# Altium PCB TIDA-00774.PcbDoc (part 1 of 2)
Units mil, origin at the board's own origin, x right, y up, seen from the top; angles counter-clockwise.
Board outline 2559.06 x 2362.2 mil, 4 copper layers (Top Layer, GND, PWR, Bottom Layer), stack 79.834 mil thick; 133 components, 91 nets, 569 pads, 616 vias.
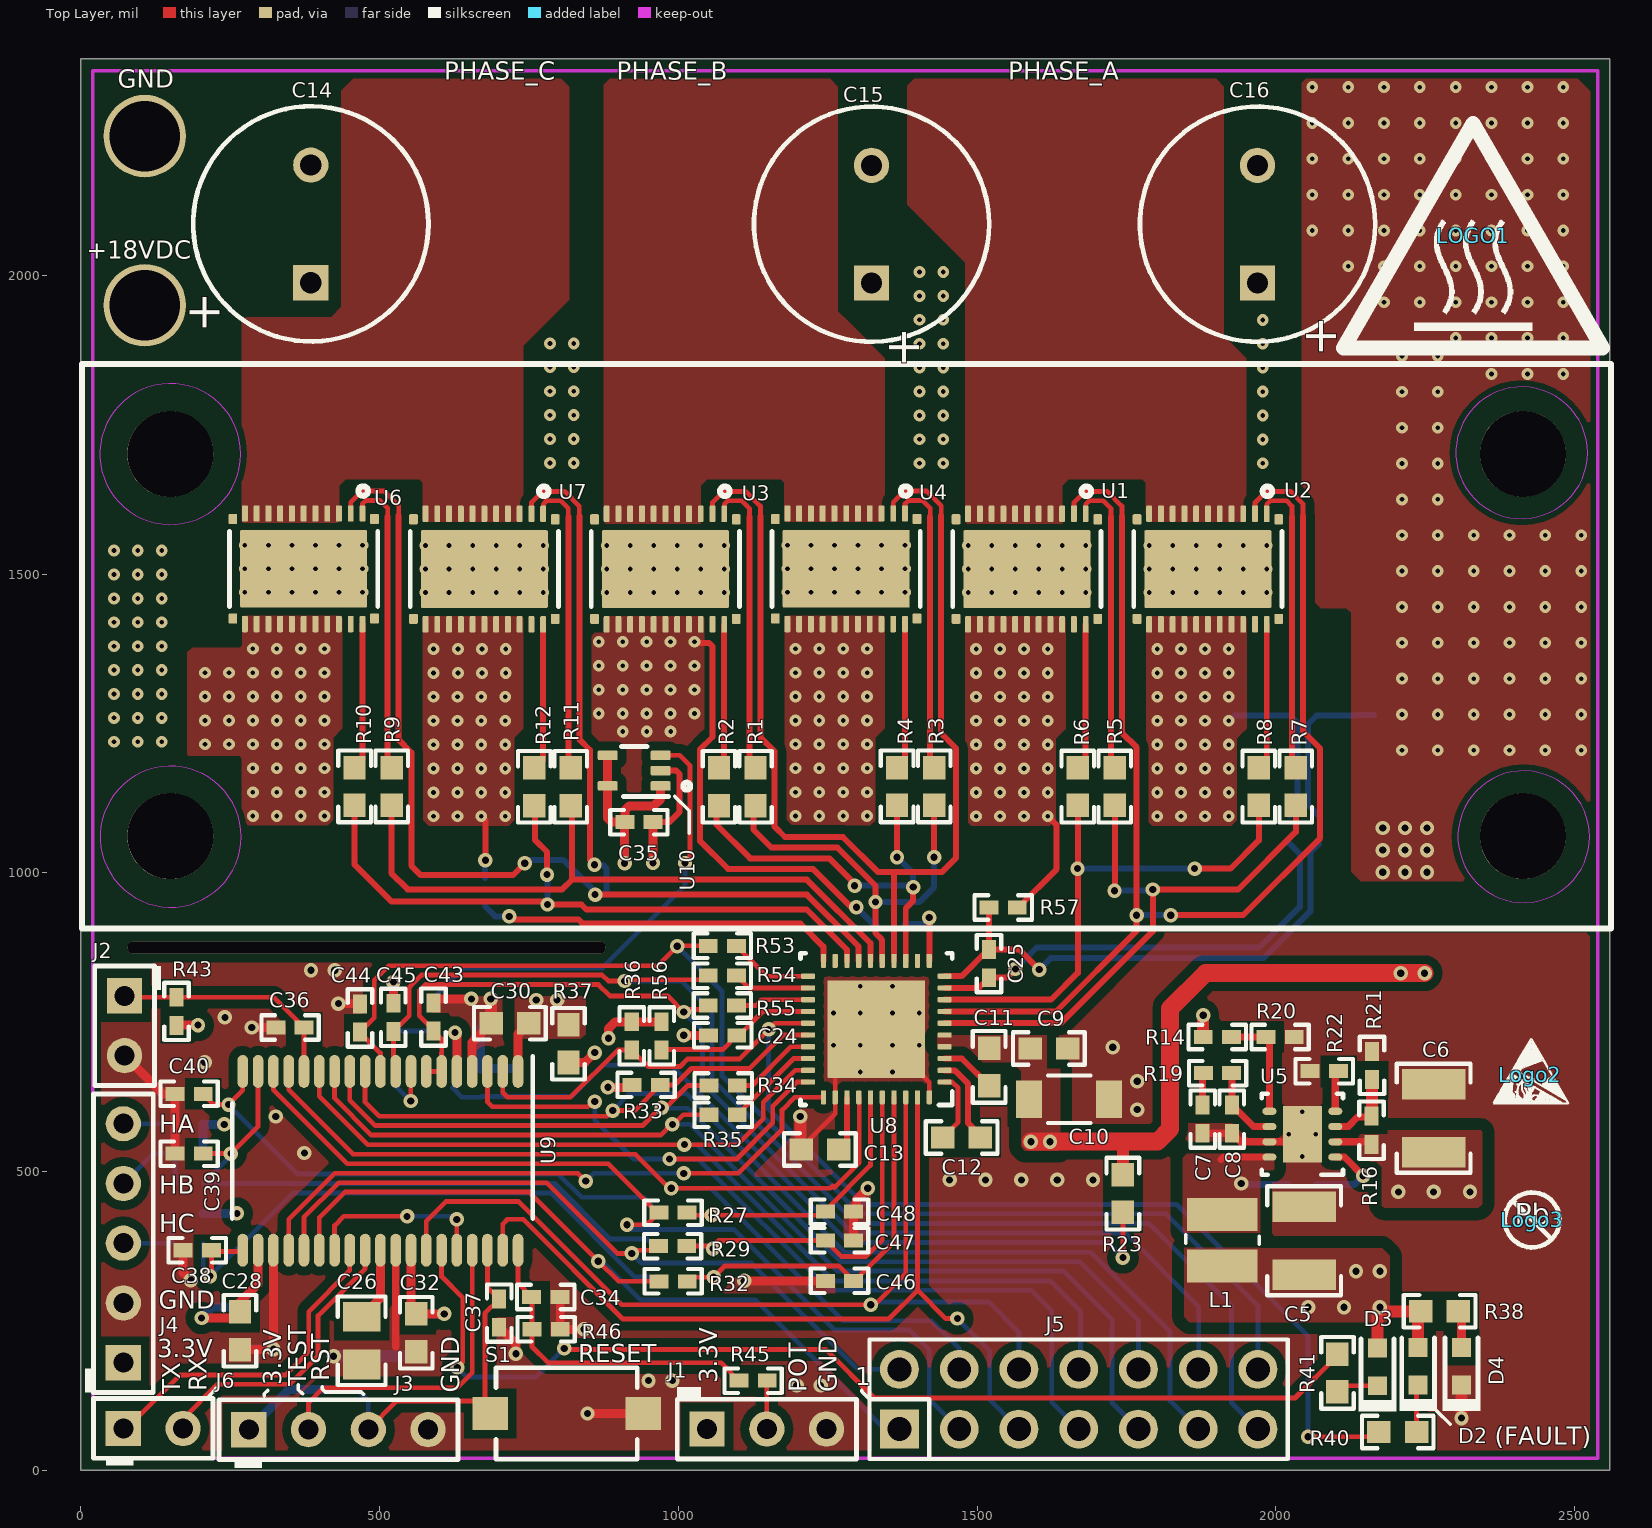
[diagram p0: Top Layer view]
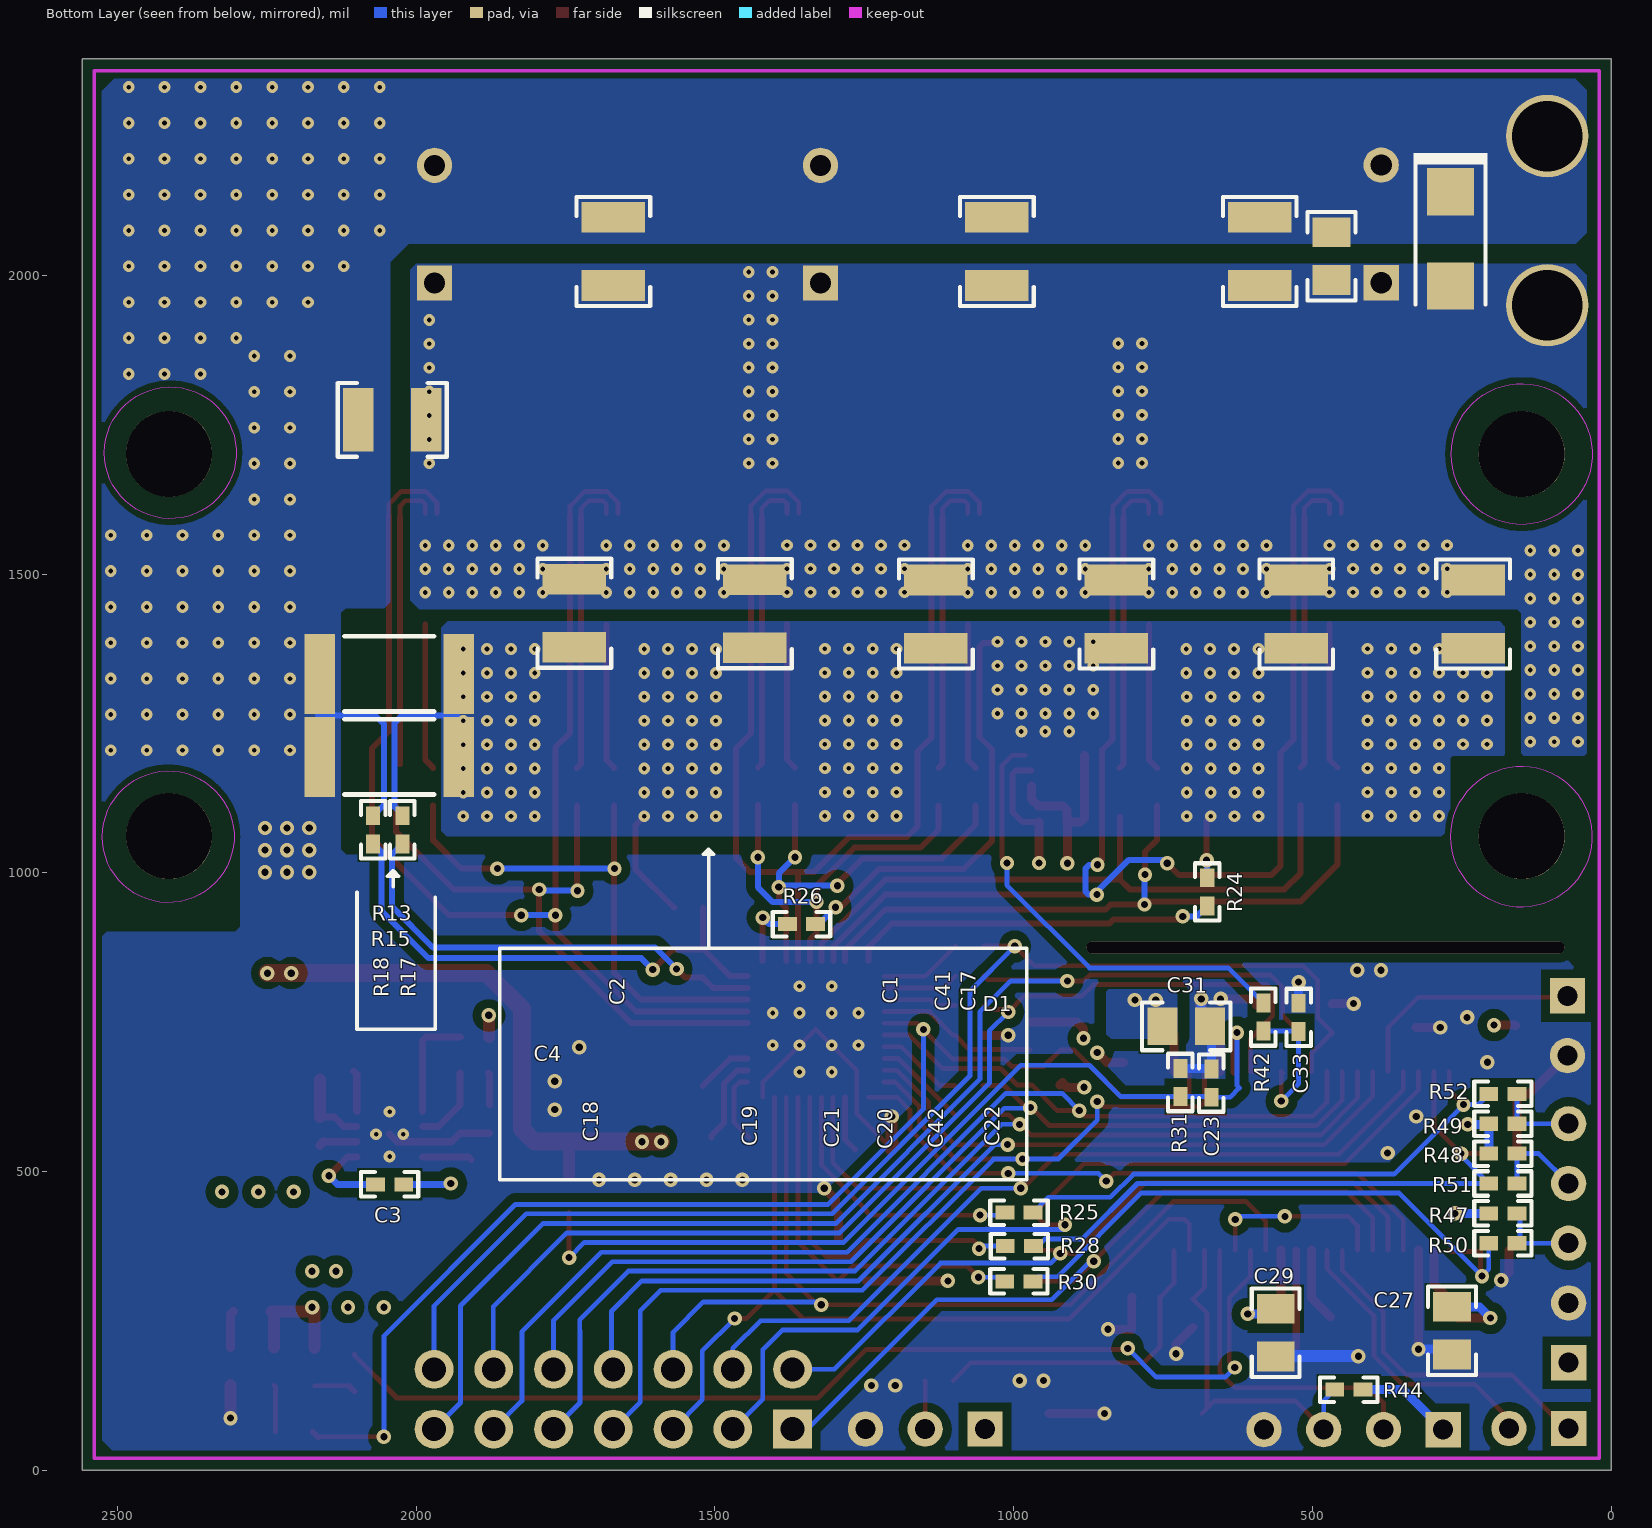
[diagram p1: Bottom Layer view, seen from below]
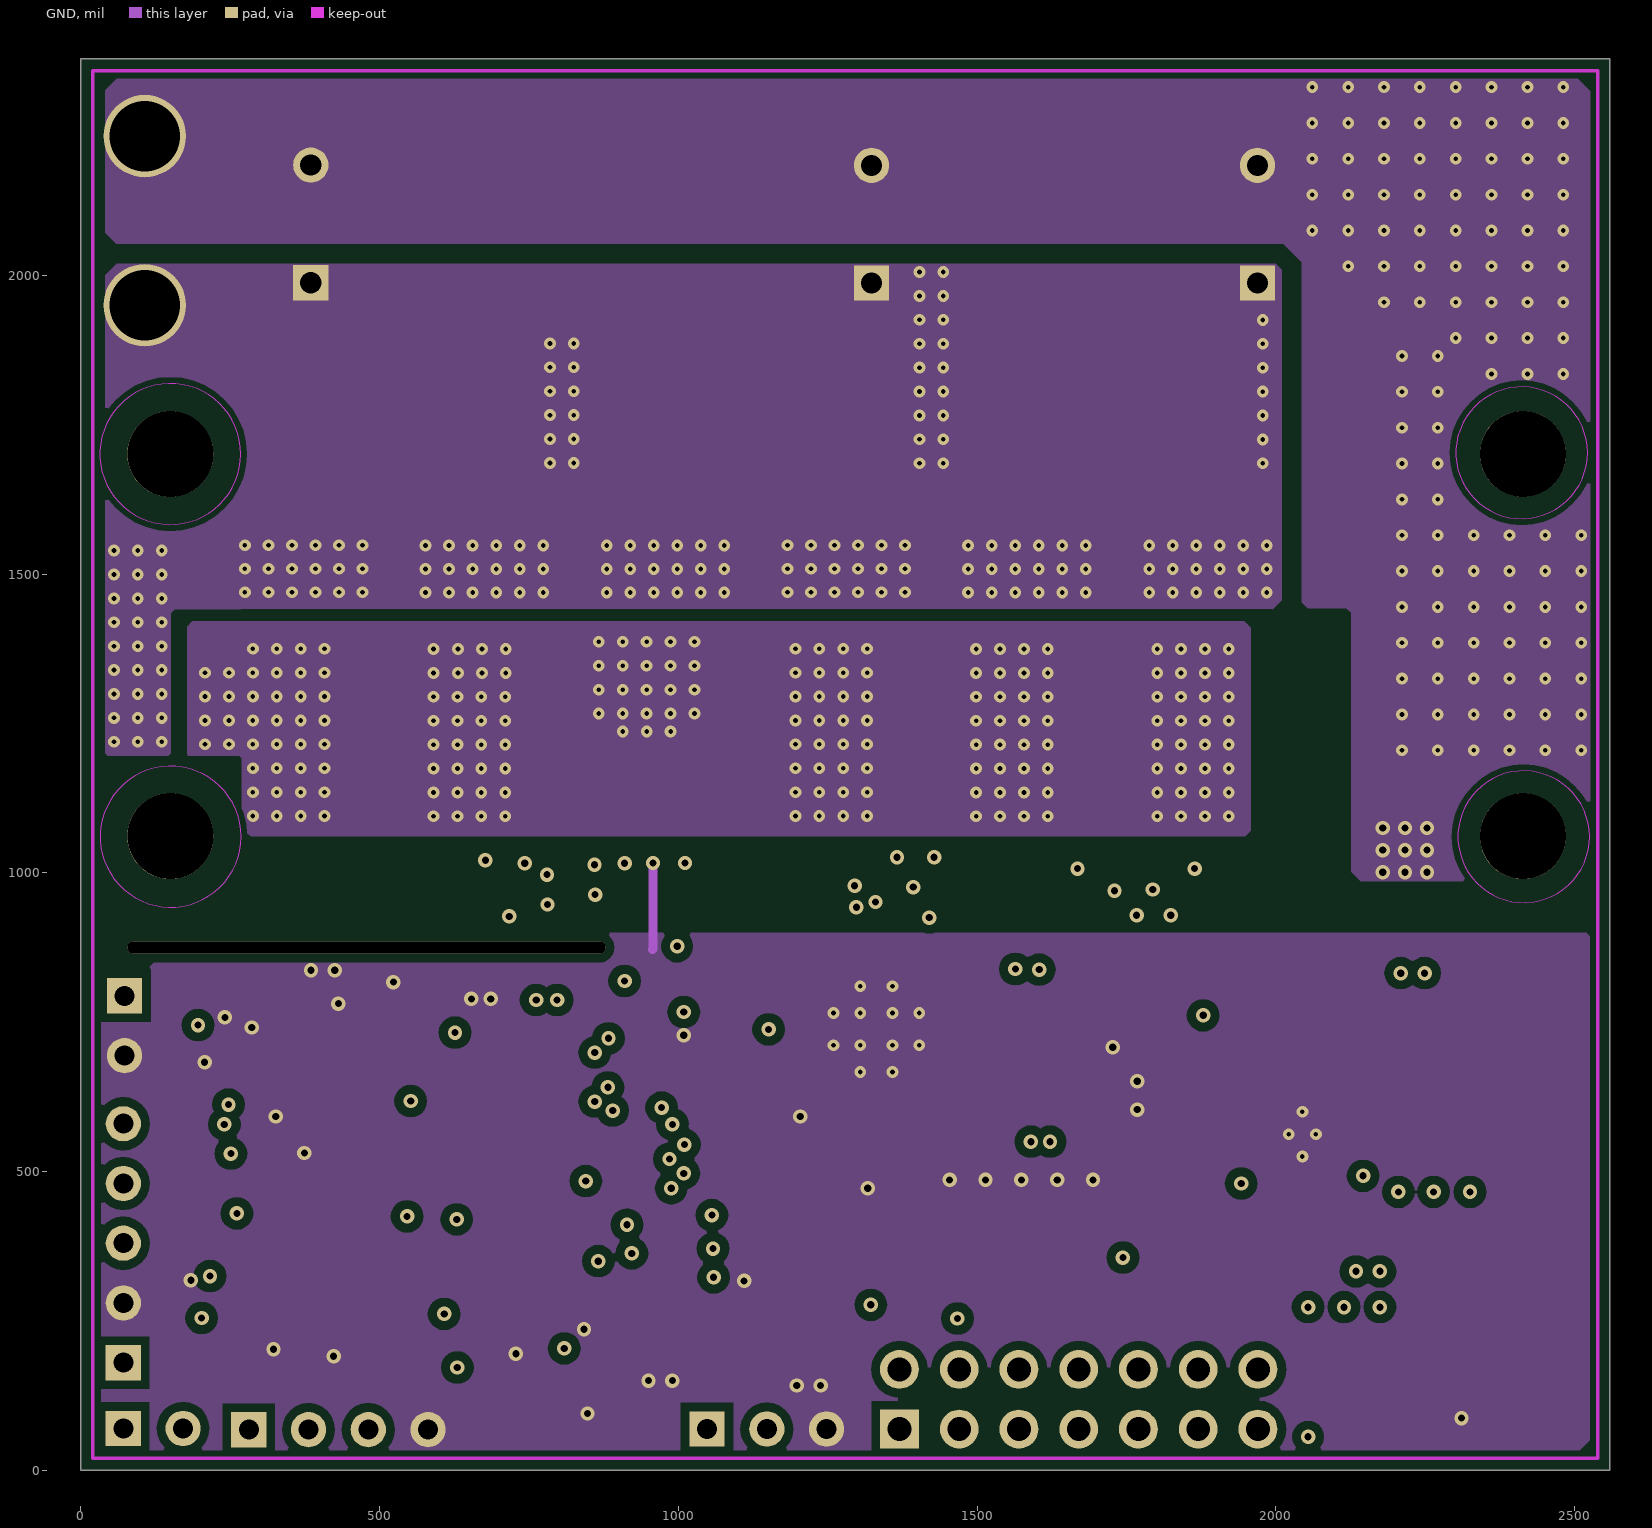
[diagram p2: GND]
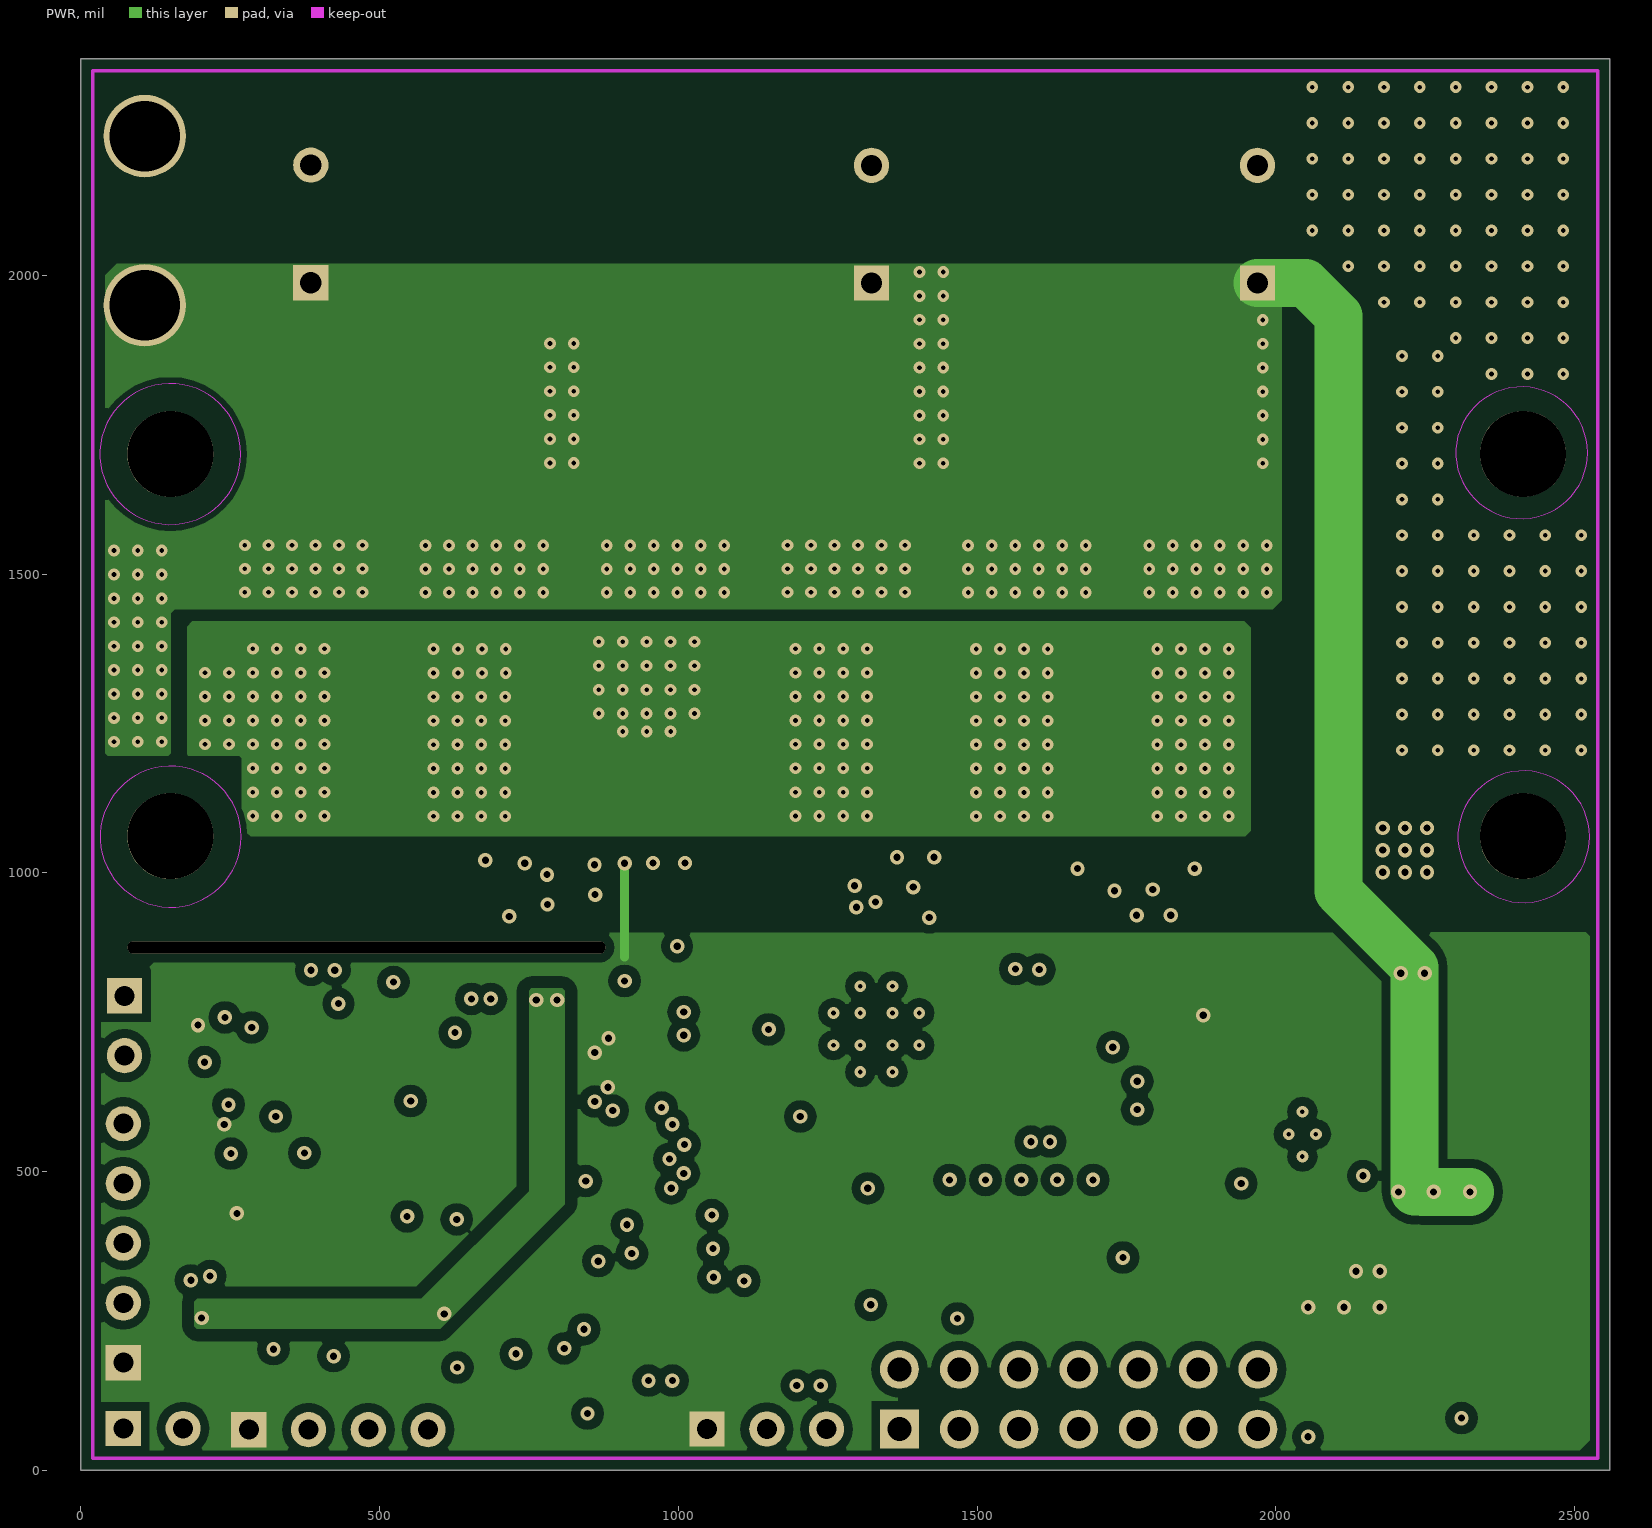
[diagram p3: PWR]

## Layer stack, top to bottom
Top Solder: solder mask 0.4, Solder Resist, Dk 3.5
Top Layer: signal copper 1.4
Dielectric1: core 59.2, FR-4, Dk 4.8
GND: signal copper 1.417
Dielectric 3: prepreg 5, Dk 4.2
PWR: signal copper 1.417
Dielectric 2: core 10, Dk 4.2
Bottom Layer: signal copper 1.4
Bottom Solder: solder mask 0.4, Solder Resist, Dk 3.5

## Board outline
0,0 2559.06,0 2559.06,2362.2 0,2362.2

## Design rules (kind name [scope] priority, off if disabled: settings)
AcuteAngle [All] p1: minimum=4.50000000000000E+0001 checktracksonly=FALSE
AssemblyTestPointUsage [All] p1: valid=2
Clearance Clearance_u1 [InPadClass('U1')] p1: gap=7.7
Clearance Clearance_Boardedge_poly [OnCopper and InPolygon vs IsKeepOut] p2: gap=10
Clearance Clearance_MTG_COPPER [InPadClass('MTG') vs InPolygon] p3: gap=40
Clearance "Shape to Shape" [InPolygon vs InPolygon] p4: gap=20
Clearance "shape to all" [InPolygon] p5: gap=15
Clearance "Clearance_via_thr pin" [IsVia vs IsThruPin] p6: gap=8
Clearance [All] p7: gap=7.8
DiffPairsRouting DiffPair_DiffPairsRouting [InDifferentialPair ('kan')] p1: maxlimit=10 minlimit=10 mostfreqgap=10 toplayer_minwidth=15 toplayer_maxwidth=15 toplayer_prefwidth=15 midlayer1_minwidth=15 midlayer1_maxwidth=15 midlayer1_prefwidth=15 midlayer2_minwidth=15 midlayer2_maxwidth=15 midlayer2_prefwidth=15 bottomlayer_minwidth=15 bottomlayer_maxwidth=15 bottomlayer_prefwidth=15 maxuncoupledlength=500
DiffPairsRouting DiffPair_DiffPairsRouting_1 [InDifferentialPair ('kan')] p2: maxlimit=10 minlimit=10 mostfreqgap=10 toplayer_minwidth=15 toplayer_maxwidth=15 toplayer_prefwidth=15 midlayer1_minwidth=15 midlayer1_maxwidth=15 midlayer1_prefwidth=15 midlayer2_minwidth=15 midlayer2_maxwidth=15 midlayer2_prefwidth=15 bottomlayer_minwidth=15 bottomlayer_maxwidth=15 bottomlayer_prefwidth=15 maxuncoupledlength=500
DiffPairsRouting [All] p3: maxlimit=100 minlimit=10 mostfreqgap=10 toplayer_minwidth=15 toplayer_maxwidth=15 toplayer_prefwidth=15 midlayer1_minwidth=15 midlayer1_maxwidth=15 midlayer1_prefwidth=15 midlayer2_minwidth=15 midlayer2_maxwidth=15 midlayer2_prefwidth=15 bottomlayer_minwidth=15 bottomlayer_maxwidth=15 bottomlayer_prefwidth=15 maxuncoupledlength=1000
FabricationTestPointUsage TestPointUsage [All] p1: valid=2 allowmultiple=FALSE
FabricationTestpoint Testpoint [All] p1: side=3 testpointundercomponent=TRUE minsize=40 maxsize=100 preferedsize=60 minholesize=0 maxholesize=40 preferedholesize=32 testpointgrid=1 allowsidetop=TRUE allowsidebottom=TRUE usegrid=TRUE gridtolerance=0.01
FanoutControl Fanout_LCC [IsLCC] p1: bgadir=Out bgaviamode=Centered fanoutstyle=Auto fanoutdirection=Alternating viagrid=1 // Fanout_LCC (Default Rule)
FanoutControl Fanout_BGA [IsBGA] p2: bgadir=Out bgaviamode=Centered fanoutstyle=Auto fanoutdirection=Alternating viagrid=1 // Fanout_BGA (Default Rule)
FanoutControl Fanout_Default [All] p4: bgadir=Out bgaviamode=Centered fanoutstyle=Auto fanoutdirection=Alternating viagrid=1 // Fanout_Default (Default Rule)
FanoutControl Fanout_Small [(CompPinCount < 5)] p5: bgadir=Out bgaviamode=Centered fanoutstyle=Auto fanoutdirection=OutThenIn viagrid=1 // Fanout_Small (Default Rule)
HoleSize [All] p1: absolutevalues=TRUE maxlimit=1000 minlimit=7 maxpercent=80.000 minpercent=20.000
MatchedLengths DiffPair_MatchedLengths [InDifferentialPair ('kan')] p1: tolerance=1000 checknetsindiffpair=TRUE checkdiffpairvsdiffpair=FALSE checkxsignals=FALSE checkothers=FALSE
MatchedLengths DiffPair_MatchedLengths_1 [InDifferentialPair ('kan')] p2: tolerance=1000 checknetsindiffpair=TRUE checkdiffpairvsdiffpair=FALSE checkxsignals=FALSE checkothers=FALSE
MinimumAnnularRing [All] p1: minimumring=5
MinimumAnnularRing MinimumAnnularRing_ThermalPadVias [IsVia and InAnyComponent] p2: minimumring=5.91
MinimumSolderMaskSliver MinimumSolderMaskSliver_Logo [InComponentClass('Logo') vs InComponentClass('Logo')] p1: minsoldermaskwidth=0.7
MinimumSolderMaskSliver [All] p2: minsoldermaskwidth=3.94
PlaneClearance [All] p1: clearance=15
PolygonConnect [All] p1: connectstyle=Direct reliefconductorwidth=10 reliefentries=4 polygonreliefangle="90 Angle" airgapwidth=10
RoutingVias RoutingVias_power [InNetClass('POWER')] p1: holewidth=16 width=32 viastyle="Through Hole" minholewidth=7.87 minwidth=19.68 maxholewidth=16 maxwidth=32
RoutingVias ThermalPadVias [IsVia and InAnyComponent] p2: holewidth=8 width=20 viastyle="Through Hole" minholewidth=7.87 minwidth=19 maxholewidth=12 maxwidth=24
RoutingVias [All] p3: holewidth=12 width=24 viastyle="Through Hole" minholewidth=7.87 minwidth=19.68 maxholewidth=16 maxwidth=32
SMDToCorner [All] p1: distance=30000
SilkToSilkClearance [All] p1: silktosilkclearance=5
SilkToSolderMaskClearance SilkscreenOverComponentPads [IsPad] p1: minsilkscreentomaskgap=0 clearancetoexposedcopper=TRUE
SolderMaskExpansion [All] p1: expansion=3
Width Width_power [InNetClass('pwr')] p1: maxlimit=200 minlimit=10 preferedwidth=20
Width [All] p2: maxlimit=100 minlimit=6 preferedwidth=10 checkconnectedcopper=TRUE
17 further rules are at their usual default settings.

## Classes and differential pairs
component class TIDA-00774_Page2: C3 C5 C6 C7 C8 C26 C27 C28 C29 C30 C31 C32 C33 C34 C35 C36 C37 C38 C39 C40 C? D2 D3 D4 J1 J2 J3 J4 J5 J6 L1 R14 R16 R19 R20 R21 R22 R37 R38 R40 R41 R42 R43 R44 R45 R46 R47 R48 R49 R50 R51 R52 R? S1 U5 U9 U10
component class TIDA-00774_Page1: C9 C10 C11 C12 C13 C14 C15 C16 C17 C23 C24 C25 C41 C43 C44 C45 C46 C47 C48 D1 R23 R24 R25 R26 R27 R28 R29 R30 R31 R32 R33 R34 R35 R36 R53 R54 R55 R56 R57 U8
component class AssemblyNote: ZZ1 ZZ2 ZZ3 ZZ4
component class TIDA-00774_Hardware: LOGO1 Logo2 Logo3 ZZ1 ZZ2 ZZ3 ZZ4
pad class U1: U1- U1-1 U1-2 U1-3 U1-4 U1-5 U1-6 U1-7 U1-8 U1-9 U1-10 U1-11 U1-12 U1-13 U1-14 U1-15 U1-16 U1-17 U1-18 U1-19 U1-20 U1-21 U1-22 U1-23 U1-24 U1-25 U1-26 U1-27 U2- U2-1 U2-2 U2-3 U2-4 U2-5 U2-6 U2-7 U2-8 U2-9 U2-10 U2-11 U2-12 U2-13 U2-14 U2-15 U2-16 U2-17 U2-18 U2-19 U2-20 U2-21 U2-22 U2-23 U2-24 U2-25 U2-26 U2-27 U3- U3-1 U3-2 U3-3 U3-4 U3-5 U3-6 U3-7 U3-8 U3-9 U3-10 U3-11 U3-12 U3-13 U3-14 U3-15 U3-16 U3-17 U3-18 U3-19 U3-20 U3-21 U3-22 U3-23 U3-24 U3-25 U3-26 U3-27 U4- U4-1 U4-2 U4-3 U4-4 U4-5 U4-6 U4-7 U4-8 U4-9 U4-10 U4-11 U4-12 U4-13 U4-14 U4-15 U4-16 U4-17 U4-18 U4-19 U4-20 U4-21 U4-22 U4-23 U4-24 U4-25 U4-26 U4-27 U6- U6-1 U6-2 U6-3 U6-4 U6-5 U6-6 U6-7 U6-8 U6-9 U6-10 U6-11 U6-12 U6-13 U6-14 U6-15 U6-16 U6-17 U6-18 U6-19 U6-20 U6-21 U6-22 U6-23 U6-24 U6-25 U6-26 U6-27 U7- U7-1 U7-2 U7-3 U7-4 U7-5 U7-6 U7-7 U7-8 U7-9 U7-10 U7-11 U7-12 U7-13 U7-14 U7-15 U7-16 U7-17 U7-18 U7-19 U7-20 U7-21 U7-22 U7-23 U7-24 U7-25 U7-26 U7-27 U9-39 U9-40 U9-41
component class TIDA-00774_Page3: C1 C2 C4 C18 C19 C20 C21 C22 C42 R1 R2 R3 R4 R5 R6 R7 R8 R9 R10 R11 R12 R13 R15 R17 R18 R? U1 U2 U3 U4 U6 U7 U?
component class Header: J1 J2 J4 J5 J6

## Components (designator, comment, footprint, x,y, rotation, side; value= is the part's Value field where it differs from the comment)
C1 "GRM32ER72A225KA35L" 1210#1 1028,2040 r90 bottom
C2 "GRM32ER72A225KA35L" 1210#1 1670,2040 r90 bottom
C3 "GRM155R71E103KA01D" 0402#1 2044.35,478.55 r0 bottom
C4 "GRM32ER72A225KA35L" 1210#1 2040,1758 r0 bottom
C5 "TMK325B7226KMHT" 1210_270 2047.36,384.24 r90 top
C6 "GRM32ER72A225KA35L" 1210#1 2264,589.31 r90 top
C7 "GRM155R71H821KA01D" 0402#1 1877.36,587.77 r270 top
C8 "CC0402JRNPO9BN150" 0402#1 1926.36,587.77 r270 top
C9 "06035C104KAT2A" 0603 1620,706 r0 top
C10 "GRM31CR71H475KA12L" 1206_180 1654,621 r180 top
C11 "C1608X7R1C105K" 0603 1520,675 r270 top
C12 "C0603C223K3RACTU" 0603 1474,557 r0 top
C13 "C1608X7R1C105K" 0603 1237,537 r180 top
C14 "35ZLG470MEFC10X20" CAPPR5-10X20 384.77,2086.09 r90 top
C15 "35ZLG470MEFC10X20" CAPPR5-10X20 1323.23,2085.61 r90 top
C16 "35ZLG470MEFC10X20" CAPPR5-10X20 1969.23,2085.61 r90 top
C17 "C2012X7R1E104K" 0805_HV 468,2032 r90 bottom
C18 "GRM32ER72A225KA35L" 1210#2 1735,1415 r270 bottom
C19 "GRM32ER72A225KA35L" 1210#2 1433,1414 r270 bottom
C20 "GRM32ER72A225KA35L" 1210#1 828,1433 r270 bottom
C21 "GRM32ER72A225KA35L" 1210#1 1130,1433 r270 bottom
C22 "GRM32ER72A225KA35L" 1210_270 231,1433 r270 bottom
C23 "885012105016" 0402#1 669,648 r90 bottom
C24 "885012105016" 0402#1 1074.19,728 r180 top
C25 "885012205061" 0402#1 1520,848 r90 top
C26 "C0805C474K4RACTU" 0805_HV 470,217 r270 top
C27 "0805YD106MAT2A" 0805_HV 266.32,233.63 r270 bottom
C28 "0603YC104JAT2A" 0603 266.32,233.63 r270 top
C29 "0805YD106MAT2A" 0805_HV 561.32,230.29 r270 bottom
C30 "0603YC104JAT2A" 0603 718.15,748 r180 top
C31 "0805YD106MAT2A" 0805_HV 711,743 r180 bottom
C32 "0603YC104JAT2A" 0603 561.32,230.29 r270 top
C33 "885012105016" 0402#1 523,758 r90 bottom
C34 "885012105016" 0402#1 778,290 r0 top
C35 "885012105016" 0402#1 934,1084.82 r0 top
C36 "885012105016" 0402#1 350,741 r180 top
C37 "GRM155R71H222KA01D" 0402#1 700,263 r270 top
C38 "885012205061" 0402#1 194.76,368.21 r180 top
C39 "885012205061" 0402#1 181,530 r180 top
C40 "885012205061" 0402#1 181,630 r180 top
C41 "GRM32ER72A225KA35L" 1210#1 588,2040 r90 bottom
C42 "GRM32ER72A225KA35L" 1210#1 527,1433 r270 bottom
C43 "CGA2B2X7R1H332K050BA" 0402#1 590,758.62 r90 top
C44 "CGA2B2X7R1H332K050BA" 0402#1 467,757 r90 top
C45 "CGA2B2X7R1H332K050BA" 0402#1 523,758 r90 top
C46 "885012205061" 0402#1 1269.65,317 r180 top
C47 "885012205061" 0402#1 1269.65,384.81 r0 top
C48 "885012205061" 0402#1 1269.65,432.81 r0 top
D1 "SMAJ30CA" SMA 268.77,2061.09 r270 bottom
D2 "150060GS75000" WL-SMCW_GREEN 2238,174 r90 top
D3 "150060GS75000" WL-SMCW_GREEN 2170,173 r90 top
D4 "150060GS75000" WL-SMCW_GREEN 2310.74,174.27 r90 top
J1 "800-10-003-10-001000" Mill-Max_800-10-003-10-001000 1148,69 r0 top
J2 "800-10-002-10-001000" Mill-Max_800-10-002-10-001000 73,744 r270 top
J3 "HEADER_1X4" Mill-Max_800-10-004-10-001000 431,68 r0 top
J4 "800-10-005-10-001000" Mill-Max_800-10-005-10-001000 71,380 r90 top
J5 "PEC07DAAN" CONN_PEC07DAAN 1670,119 r0 top
J6 "800-10-002-10-001000" Mill-Max_800-10-002-10-001000 121,70 r0 top
L1 "SDR0302-121KL" SDR0302 1910,385 r270 top
LOGO1 "CAUTION HOT SURFACE" IEC_HotSurface_medium 2330,2066 r0 top
Logo2 "ESD Susceptible" ESD_Overlay_small 2426,662 r0 top
Logo3 "Pb-Free Symbol" Pb-Free_Overlay_small 2429,419 r0 top
R1 "CRCW06033R30JNEA" 0603 1129,1144 r270 top
R2 "CRCW06033R30JNEA" 0603 1068,1144 r270 top
R3 "CRCW06033R30JNEA" 0603 1428,1144.7 r270 top
R4 "CRCW06033R30JNEA" 0603 1366,1144.7 r270 top
R5 "CRCW06033R30JNEA" 0603 1730.45,1144.22 r270 top
R6 "CRCW06033R30JNEA" 0603 1668.45,1144.22 r270 top
R7 "CRCW06033R30JNEA" 0603 2033.45,1144.22 r270 top
R8 "CRCW06033R30JNEA" 0603 1971.45,1144.22 r270 top
R9 "CRCW06033R30JNEA" 0603 520,1144.7 r270 top
R10 "CRCW06033R30JNEA" 0603 458,1144.7 r270 top
R11 "CRCW06033R30JNEA" 0603 820,1144 r270 top
R12 "CRCW06033R30JNEA" 0603 759,1144 r270 top
R13 "CSNL2512FT2L00" 2512 2045,1333 r0 bottom
R14 "CRCW040230K9FKED" 0402#1 1902,725.31 r180 top
R15 "CSNL2512FT2L00" 2512 2045,1194 r0 bottom
R16 "CRCW0402196KFKED" 0402#1 2160.12,569.13 r270 top
R17 "ERJ-2RKF1000X" 0402#1 2023,1072 r90 bottom
R18 "ERJ-2RKF1000X" 0402#1 2072,1072 r90 bottom
R19 "CRCW040253K6FKED" 0402#1 1902.36,664.77 r0 top
R20 "CRCW040210K0FKED" 0402#1 2007,725.31 r180 top
R21 "CRCW040249K9FKED" 0402#1 2161,677.53 r270 top
R22 "CRCW040297K6FKED" 0402#1 2081,668.11 r0 top
R23 "RC0603FR-0734K8L" 0603 1744,463 r90 top
R24 "CRCW04020000Z0ED" 0402#1 676,968 r270 bottom
R25 "ERJ-2RKF1000X" 0402#1 990.96,431.21 r0 bottom
R26 "CRCW04020000Z0ED" 0402#1 1355,914 r0 bottom
R27 "ERJ-2RKF1000X" 0402#1 990.96,431.21 r0 top
R28 "ERJ-2RKF1000X" 0402#1 990.24,375.21 r0 bottom
R29 "ERJ-2RKF1000X" 0402#1 990.24,375.21 r0 top
R30 "ERJ-2RKF1000X" 0402#1 991.24,316.21 r0 bottom
R31 "ERJ-2RKF2201X" 0402#1 721,649 r270 bottom
R32 "ERJ-2RKF1000X" 0402#1 991.24,316.21 r0 top
R33 "CRCW040210K0FKED" 0402#1 946,645 r0 top
R34 "ERJ-2RKF1000X" 0402#1 1075,644 r180 top
R35 "ERJ-2RKF1000X" 0402#1 1075,595 r180 top
R36 "CRCW040210K0FKED" 0402#1 922,727 r270 top
R37 "CRCW06033R30JNEA" 0603 816,714 r90 top
R38 "CRCW06031K00JNEA" 0603 2274,266 r180 top
R40 "CRCW06031K00JNEA" 0603 2204,64 r0 top
R41 "CRCW06031K00JNEA" 0603 2103,163 r270 top
R42 "CRCW040210K0FKED" 0402#1 582,758.62 r90 bottom
R43 "ERJ-2RKF1004X" 0402#1 160,768 r90 top
R44 "CRCW040247K5FKED" 0402#1 439,135 r180 bottom
R45 "CRCW040210K0FKED" 0402#1 1125,150 r0 top
R46 "ERJ-2RKF1004X" 0402#2 -754.68,1254.3 r90 top
R47 "CRCW04023K30JNED" 0402#1 181,430 r0 bottom
R48 "CRCW04023K30JNED" 0402#1 181,530 r0 bottom
R49 "CRCW04023K30JNED" 0402#1 181,580 r0 bottom
R50 "ERJ-2RKF1000X" 0402#1 181,380 r180 bottom
R51 "ERJ-2RKF1000X" 0402#1 181,480 r180 bottom
R52 "ERJ-2RKF1000X" 0402#1 181,630 r180 bottom
R53 "ERJ-2RKF1000X" 0402#1 1073.56,877.81 r180 top
R54 "ERJ-2RKF1000X" 0402#1 1073.56,827.81 r180 top
R55 "ERJ-2RKF1000X" 0402#1 1073.56,777.81 r180 top
R56 "CRCW04020000Z0ED" 0402#1 972,727 r270 top
R57 "CRCW04020000Z0ED" 0402#1 1543.62,942 r180 top
S1 "434121025816" SW_434121025816 813,95 r180 top
U1 "CSD88584Q5DC" DMM0022A 1583.3,1508.37 r270 top locked
U2 "CSD88584Q5DC" DMM0022A 1886.3,1508.37 r270 top locked
U3 "CSD88584Q5DC" DMM0022A 978.3,1508.37 r270 top locked
U4 "CSD88584Q5DC" DMM0022A 1280.85,1508.85 r270 top locked
U5 "TPS54061DRB" DRB0008B 2044.35,562.53 r180 top
U6 "CSD88584Q5DC" DMM0022A 372.85,1508.85 r270 top
U7 "CSD88584Q5DC" DMM0022A 675.24,1508.37 r270 top locked
U8 "DRV8323SRHAR" RHA0040B 1331.33,738.4 r180 top
U9 "MSP430F5132IDA" DA0038A_N 501.3,518 r270 top
U10 "LMT87QDCKRQ1" DCK0005A_N 926,1171 r180 top
ZZ1 "This Assembly Note is for PCB labels only" AssemblyNoteLabel -645,3011 r0 top
ZZ2 "These assemblies are ESD sensitive, ESD precautions shall be observed." AssemblyNote -651.15,2948.85 r0 top
ZZ3 "These assemblies must be clean and free from flux and all contaminants. Use of no clean flux is not acceptable." AssemblyNote -651.15,2873.85 r0 top
ZZ4 "These assemblies must comply with workmanship standards IPC-A-610 Class 2, unless otherwise specified." AssemblyNote -649.15,2802.85 r90 top

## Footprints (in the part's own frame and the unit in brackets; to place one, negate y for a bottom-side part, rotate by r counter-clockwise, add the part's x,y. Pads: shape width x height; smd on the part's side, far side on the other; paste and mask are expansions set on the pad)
0402#1 [mm] "0402 from SM-752 data"
  rect 0.8x0.6 smd: 1(-0.6,0) 2(0.6,0)
  silkscreen extent -1.22,-0.52 1.22,0.52, body extent -0.55,-0.3 0.55,0.3, height 0.6
0402#2 [mm] "0402 from SM-752 data"
  rect 0.6x0.8 smd: 1(-25.865,-39.546) 2(-25.865,-38.346)
  silkscreen extent -26.39,-40.17 -25.34,-37.73, body extent -26.16,-39.5 -25.57,-38.4, height 0.6
0603 [mm] "0603 from SM-752 data"
  rect 1x0.95 smd: 1(-0.8,0) 2(0.8,0)
  silkscreen extent -1.52,-0.69 1.52,0.69, body extent -0.87,-0.47 0.87,0.47, height 1
0805_HV [mil] "0805 with 30mil clearance between pads"
  rect 50x63 smd: 1(-40,0) 2(40,0)
  silkscreen extent -74,-40 74,40, body extent -43,-29 43,29, height 57
1206_180 [mm] "1206_180"
  rect 1.1x1.6 smd: 1(-1.7,0) 2(1.7,0)
  silkscreen extent -0.9,-1 0.9,1, body extent -1.75,-0.95 1.75,0.95, height 1.8
1210#1 [mm] "1210 from SM-752 data"
  rect 1.3x2.7 smd: 1(-1.45,0) 2(1.45,0)
  silkscreen extent -2.32,-1.57 2.32,1.57, body extent -1.7,-1.35 1.7,1.35, height 1.35
1210#2 [mm] "1210 from SM-752 data"
  rect 1.3x2.7 smd: 1(-1.945,0) 2(0.955,0)
  silkscreen extent -2.81,-1.57 1.82,1.57, body extent -2.19,-1.35 1.2,1.35, height 1.35
1210_270 [mm] "1210"
  rect 1.3x2.7 smd: 1(-1.45,0) 2(1.45,0)
  silkscreen extent -2.32,-1.57 2.32,1.57, body extent -1.7,-1.35 1.7,1.35, height 2.7
2512 [mm] "Chip Resistor, Body 6.3x3.2mm, IPC Medium Density"
  rect 1.3x3.4 smd: 1(-2.95,0) 2(2.95,0)
  silkscreen extent -1.9,-1.6 1.9,1.6, body extent -3.22,-1.67 3.22,1.67, height 0.71
AssemblyNote [mil] "Assembly Note"
AssemblyNoteLabel [mil] "Assembly Note for PCB Labels"
CAPPR5-10X20 [mm] "Capacitor, Electrolytic, Radial; Body 10 x 20 mm (Dia.xH typ); Pin Spacing 5 mm (typ)"
  rect 1.5x1.5 hole 0.9: 1(-2.5,0)
  round 1.5 hole 0.9: 2(2.5,0)
  silkscreen extent -5,-5 5,5, body extent -5,-5 5,5, height 22
CONN_PEC07DAAN [mm] "SULLINS"
  rect 1.65x1.65 hole 1.016 mask+0: 1(-7.62,-1.27)
  round 1.65 hole 1.016 mask+0: 2(-7.62,1.27) 3(-5.08,-1.27) 4(-5.08,1.27) 5(-2.54,-1.27) 6(-2.54,1.27) 7(0,-1.27) 8(0,1.27) 9(2.54,-1.27) 10(2.54,1.27) 11(5.08,-1.27) 12(5.08,1.27) 13(7.62,-1.27) 14(7.62,1.27)
  silkscreen extent -8.89,-2.54 8.89,2.54, body extent -8.95,-2.6 8.95,2.6, height 11.43
DA0038A_N [mm] "TSOP, 38-Leads, Body 12.6x6.2mm (max), Pitch 0.65mm, IPC Medium Density"
  oval 1.4x0.45 smd mask+0.051: 1(-3.8,5.85) 2(-3.8,5.2) 3(-3.8,4.55) 5(-3.8,3.25) 6(-3.8,2.6) 7(-3.8,1.95) 8(-3.8,1.3) 9(-3.8,0.65) 10(-3.8,0) 11(-3.8,-0.65) 12(-3.8,-1.3) 13(-3.8,-1.95) 14(-3.8,-2.6) 15(-3.8,-3.25) 16(-3.8,-3.9) 17(-3.8,-4.55) 18(-3.8,-5.2) 19(-3.8,-5.85) 20(3.8,-5.85) 21(3.8,-5.2) 22(3.8,-4.55) 23(3.8,-3.9) 24(3.8,-3.25) 25(3.8,-2.6) 26(3.8,-1.95) 27(3.8,-1.3) 28(3.8,-0.65) 29(3.8,0) 30(3.8,0.65) 31(3.8,1.3) 32(3.8,1.95) 33(3.8,2.6) 34(3.8,3.25) 35(3.8,3.9) 36(3.8,4.55) 37(3.8,5.2) 38(3.8,5.85)
  oval 1.4x0.45 smd paste+0 mask+0.051: 4(-3.8,3.9)
  silkscreen extent -4.45,-6.3 2.45,6.48, body extent -4.06,-6.25 4.06,6.25, height 1.2
DCK0005A_N [mm] "SOT353, 5-Leads, Body 2x1.3mm, Pitch 0.65mm, Lead Span 2.1mm, IPC Medium Density"
  rrect25% 0.85x0.4 smd: 1(-1.125,0.65) 2(-1.125,0) 3(-1.125,-0.65) 4(1.125,-0.65) 5(1.125,0.65)
  silkscreen extent -1.48,-1.02 0.55,1.1, body extent -1.14,-1 1.14,1, height 0.95
DMM0022A [mm] "SON, 27-Leads, Body 5x6mm, Pitch 0.5mm"
  rrect40% 0.7x0.25 smd mask+0.051: 1(-2.35,2.5) 2(-2.35,2) 21(2.35,2) 22(2.35,2.5)
  rrect40% 0.7x0.25 smd mask+0: 3(-2.35,1.5) 4(-2.35,1) 5(-2.35,0.5) 6(-2.35,0) 7(-2.35,-0.5) 8(-2.35,-1) 9(-2.35,-1.5) 10(-2.35,-2) 11(-2.35,-2.5) 12(2.35,-2.5) 13(2.35,-2) 14(2.35,-1.5) 15(2.35,-1) 16(2.35,-0.5) 17(2.35,0) 18(2.35,0.5) 19(2.35,1) 20(2.35,1.5)
  rrect27% 0.43x0.375 smd mask+0.051: 23(-2.115,3.013) 24(-2.115,-3.013) 25(2.115,-3.013) 26(2.115,3.013)
  rrect3% 3.3x5.4 smd paste-1.65: 27(0,0)
  rrect50% 1.41x1.12 on Top Paste: ""(-0.805,1.98) ""(-0.805,0.66) ""(-0.805,-0.66) ""(-0.805,-1.98) ""(0.805,1.98) ""(0.805,0.66) ""(0.805,-0.66) ""(0.805,-1.98)
  silkscreen extent -1.6,-3.15 1.6,3.15, body extent -2.55,-3.05 2.55,3.05, height 1.05
DRB0008B [mm] "SON, 8-Leads, Body 3x3mm, Pitch 0.65mm, Thermal Pad 2.4x1.65mm, TI Recommended"
  oval 0.6x0.3 smd: 1(-1.4,0.975) 2(-1.4,0.325) 3(-1.4,-0.325) 4(-1.4,-0.975) 5(1.4,-0.975) 6(1.4,-0.325) 7(1.4,0.325) 8(1.4,0.975)
  rect 1.65x2.4 smd paste-1.2: 9(0,0)
  silkscreen extent -1.73,-1.73 1.73,1.73, body extent -1.57,-1.57 1.58,1.58, height 1.01
ESD_Overlay_small [mil]
  silkscreen extent -62,-48 64,61
IEC_HotSurface_medium [mil]
  silkscreen extent -217,-188 217,188
Mill-Max_800-10-002-10-001000 [mm] "Mill-Max"
  rect 1.5x1.5 hole 0.85: 1(-1.27,0)
  round 1.5 hole 0.85: 2(1.27,0)
  silkscreen extent -2.54,-1.27 2.54,1.55, body extent -2.54,-1.27 2.54,1.27, height 8.13
Mill-Max_800-10-003-10-001000 [mm] "Mill-Max"
  rect 1.5x1.5 hole 0.85: 1(-2.54,0)
  round 1.5 hole 0.85: 2(0,0) 3(2.54,0)
  silkscreen extent -3.81,-1.27 3.81,1.78, body extent -3.81,-1.27 3.81,1.27, height 8.13
Mill-Max_800-10-004-10-001000 [mm] "Mill-Max"
  rect 1.5x1.5 hole 0.85: 1(-3.81,0)
  round 1.5 hole 0.85: 2(-1.27,0) 3(1.27,0) 4(3.81,0)
  silkscreen extent -5.08,-1.27 5.08,1.27, body extent -5.08,-1.27 5.08,1.27, height 8.13
Mill-Max_800-10-005-10-001000 [mm] "Mill-Max"
  rect 1.5x1.5 hole 0.85: 1(-5.08,0)
  round 1.5 hole 0.85: 2(-2.54,0) 3(0,0) 4(2.54,0) 5(5.08,0)
  silkscreen extent -6.35,-1.27 6.35,1.63, body extent -6.35,-1.27 6.35,1.27, height 8.13
Pb-Free_Overlay_small [mil]
  silkscreen extent -46,-46 46,46
RHA0040B [mm] "QFN, 40-Leads, Body 6x6mm, Pitch 0.5mm, Thermal Pad 4.15 x 4.15mm, TI Recommended"
  rrect45% 0.6x0.22 smd mask+0.07: 1(-2.9,2.25) 2(-2.9,1.75) 3(-2.9,1.25) 4(-2.9,0.75) 5(-2.9,0.25) 6(-2.9,-0.25) 7(-2.9,-0.75) 8(-2.9,-1.25) 9(-2.9,-1.75) 10(-2.9,-2.25) 21(2.9,-2.25) 22(2.9,-1.75) 23(2.9,-1.25) 24(2.9,-0.75) 25(2.9,-0.25) 26(2.9,0.25) 27(2.9,0.75) 28(2.9,1.25) 29(2.9,1.75) 30(2.9,2.25)
  rrect45% 0.22x0.6 smd mask+0.07: 11(-2.25,-2.9) 12(-1.75,-2.9) 13(-1.25,-2.9) 14(-0.75,-2.9) 15(-0.25,-2.9) 16(0.25,-2.9) 17(0.75,-2.9) 18(1.25,-2.9) 19(1.75,-2.9) 20(2.25,-2.9) 31(2.25,2.9) 32(1.75,2.9) 33(1.25,2.9) 34(0.75,2.9) 35(0.25,2.9) 36(-0.25,2.9) 37(-0.75,2.9) 38(-1.25,2.9) 39(-1.75,2.9) 40(-2.25,2.9)
  rrect9% 1.17x1.17 on Top Paste: 41(-1.37,1.37) 41(-1.37,0) 41(-1.37,-1.37) 41(0,1.37) 41(0,0) 41(0,-1.37) 41(1.37,1.37) 41(1.37,0) 41(1.37,-1.37)
  rrect2% 4.15x4.15 smd paste-2.1: 41(0,0)
  silkscreen extent -3.22,-3.22 3.22,3.22, body extent -3,-3 3,3, height 1
SDR0302 [mm] "BOURNS"
  rect 1.4x3 smd: 1(-1.1,0) 2(1.1,0)
  body extent -1.65,-1.65 1.65,1.65, height 2.8
SMA [mm] "Molded Diode, 2-Leads, Body 4.3x2.6mm, IPC Medium Density, based on OnSemi component dimensions and land pattern"
  rect 2x2 smd: 1(-2,0) 2(2,0)
  silkscreen extent -3.66,-1.57 2.79,1.57, body extent -2.6,-1.3 2.6,1.3, height 2.42
SW_434121025816 [mm] "SMD, 2-Leads, Body 6x3.9mm, Pitch 6.5mm"
  rect 1.5x1.4 smd: 1(-3.25,0) 2(3.25,0)
  silkscreen extent -3,-1.95 3,1.95, body extent -3.65,-1.95 3.65,1.95, height 2.5
WL-SMCW_GREEN [mm] "WURTH"
  rect 0.8x0.8 smd: 1(-0.8,0) 2(0.8,0)
  silkscreen extent -1.9,-0.8 1.2,0.8, body extent -0.85,-0.45 0.85,0.45, height 0.8

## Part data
C1 C2 C4 C18 C19 C20 C21 C22 C41 C42: "CAP, CERM, 2.2 µF, 100 V, +/- 10%, X7R, 1210"
C3: "CAP, CERM, 0.01 µF, 25 V, +/- 10%, X7R, 0402"
C5: "CAP, CERM, 22 µF, 25 V, +/- 10%, X7R, AEC-Q200 Grade 1, 1210"
C6: "CAP, CERM, 2.2uF, 100V, +/-10%, X7R, 1210"
C7: "CAP, CERM, 820 pF, 50 V, +/- 10%, X7R, 0402"
C8: "CAP, CERM, 15 pF, 50 V, +/- 5%, C0G/NP0, 0402"
C9: "CAP, CERM, 0.1 µF, 50 V, +/- 10%, X7R, 0603"
C10: "CAP, CERM, 4.7 µF, 50 V, +/- 10%, X7R, 1206"
C11 C13: "CAP, CERM, 1 µF, 16 V, +/- 10%, X7R, 0603"
C12: "CAP, CERM, 0.022 µF, 25 V, +/- 10%, X7R, 0603"
C14 C15 C16: library part 35ZL470MEFC10X20, "470µF 35V CAP ALUM CAN 4000 Hrs @ 105°C"
C17: "CAP, CERM, 0.1 µF, 50 V, +/- 10%, X7R, 0805"
C23 C24 C33 C34 C35 C36: "CAP, CERM, 0.1 µF, 16 V, +/- 20%, X5R, 0402"
C25 C38 C39 C40 C46 C47 C48: "CAP, CERM, 1000 pF, 50 V, +/- 10%, X7R, 0402"
C26: "CAP, CERM, 0.47 µF, 16 V, +/- 10%, X7R, 0805"
C27 C29 C31: "CAP, CERM, 10uF, 16V, +/-20%, X5R, 0805"
C28 C30 C32: "CAP, CERM, 0.1 µF, 16 V, +/- 5%, X7R, 0603"
C37: "CAP, CERM, 2200 pF, 50 V, +/- 10%, X7R, 0402"
C43 C44 C45: "CAP, CERM, 3300 pF, 50 V, +/- 10%, X7R, AEC-Q200 Grade 1, 0402"
D1: "Diode, TVS, Bi, 30 V, 400 W, SMA"
D2: "LED RED CLEAR 0603 SMD"
D3: "LED YELLOW CLEAR 0603 SMD"
D4: "LED, Green, SMD"
J1: "Header, 100mil, 3x1, TH"
J2 J6: "Header, 100mil, 2x1, TH"
J3: "Header, Male 4-pin, 100mil spacing,"
J4: "Header, 100mil, 5x1, TH"
J5: "Header, 100mil, 7x2, Tin, TH"
L1: "Inductor, Drum Core, Ferrite, 120uH, 0.22A, 3.2 ohm, SMD"
LOGO1: library part IEC_HotSurface, "IEC 61010-1 Hot Surface Warning"
Logo2: library part ESD_Susceptible, "ESD Susceptible Symbol"
Logo3: library part Pb-Free
R1 R2 R3 R4 R5 R6 R7 R8 R9 R10 R11 R12 R37: "RES, 3.3, 5%, 0.1 W, 0603"
R13 R15: "RES SMD 0.001 OHM 1% 5W 2512"
R14: "RES, 30.9k ohm, 1%, 0.063W, 0402"
R16: "RES, 196 k, 1%, 0.063 W, 0402"
R17 R18 R25 R27 R28 R29 R30 R32 R34 R35 R50 R51 R52 R53 R54 R55: "RES, 100, 1%, 0.1 W, 0402"
R19: "RES, 53.6 k, 1%, 0.063 W, 0402"
R20: "RES, 10.0k ohm, 1%, 0.063W, 0402"
R21: "RES, 49.9 k, 1%, 0.063 W, 0402"
R22: "RES, 97.6k ohm, 1%, 0.063W, 0402"
R23: "RES SMD 2M OHM 1% 1/10W 0603"
R24 R26 R56 R57: "RES, 0, 5%, 0.063 W, 0402"
R31: "RES SMD 300K OHM 1% 1/16W 0402"
R33 R36 R42 R45: "RES, 10.0 k, 1%, 0.063 W, 0402"
R38 R40 R41: "RES, 1.0 k, 5%, 0.1 W, 0603"
R43 R46: "RES, 1.00 M, 1%, 0.1 W, 0402"
R44: "RES, 47.5 k, 1%, 0.063 W, 0402"
R47 R48 R49: "RES, 3.3 k, 5%, 0.063 W, 0402"
S1: "Switch, Tactile, SPST, 12 V, SMD"
U1 U2 U3 U4 U6 U7: "40 V Half-Bridge NexFE Power Block, DMM0022A"
U5: "IC, 60V/0.2A  Synchronous Buck Regulator"
U8: "60-V Three-Phase Smart Gate Driver, RHA0040B"
U9: "25 MHz Mixed Signal Microcontroller with 8 KB Flash, 1024 B SRAM and 29 GPIOs, -40 to 85 degC, 38-pin SOP (DA), Green (RoHS & no Sb/Br)"
U10: "SC70 Analog Temperature Sensor with Class-AB Output, DCK0005A"
ZZ1: library part AssemblyNoteLabel
ZZ2 ZZ3 ZZ4: library part AssemblyNote

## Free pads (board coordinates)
  round 138.11 hole 118.11: 0(106.83,1950.05) 1(106.83,2233.05)
  round 143.86 hole 143.86 unplated mask+20: 1(149.64,1700.91) 1(2413.4,1701) 2(149.64,1061.3) 2(2413.42,1061.3)
  oval 800x20 hole 20 slot 800 at 0 deg unplated mask+5: 5(478,875)

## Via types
v1: diameter 19.68, hole 7.87, Top Layer to Bottom Layer, 491 vias
v2: diameter 24, hole 12, Top Layer to Bottom Layer, tented both sides, 125 vias

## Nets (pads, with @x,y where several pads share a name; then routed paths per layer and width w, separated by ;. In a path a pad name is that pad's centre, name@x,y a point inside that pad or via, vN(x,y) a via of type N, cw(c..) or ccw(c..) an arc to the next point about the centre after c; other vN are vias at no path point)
3.3V: C5.1 C35.1 D2.2 D3.2 J1.1 J3.1 J4.1 L1.2 R14.2 R33.1 R36.1 R37.1 R38.2 R43.1 R44.2 R47.2 R48.2 R49.2 R56.1 U10.1 U10.4 U10.5 | length 1258.3
  Top Layer w15: R43.1@160,744.38 160.62,745 v2(196,745) ; R37.1@816,682.5 843.5,682.5 v2(860,699) ; U10.4@881.71,1196.59 881.71,1091.29 888.18,1084.82 C35.1@910.38,1084.82 ; v2(882,641) 910.38,641 918.38,649 R33.1@922.38,645 ; v2(883,723) 883,739 894.62,750.62 R36.1@922,750.62 R56.1@972,750.62 ; v2(910,1016) 910,1084.44 C35.1@910.38,1084.82 ; U10.1@970.29,1145.41 970.29,1123.29 959,1112 918,1112 910.38,1104.38 C35.1@910.38,1084.82
  Top Layer w20: R14.2@1878.38,725.31 v2(1878.36,761.45) ; D3.2@2170,204.5 2170,269 v2(2174,273) 2181,266 R38.2@2242.5,266 2238,261.5 D2.2@2238,205.5
  PWR w15: 910,859.4 v2(910,1016)
  Bottom Layer w15: R47.2@204.62,430 v2(261,430) ; R48.2@204.62,530 R49.2@204.62,580 205.62,579 v2(240,579) ; J3.1@281,68 348,135 R44.2@415.38,135
  other v2: 2054,273 2114,273 2134,333 2174,333
CAL: U8.31 U9.23 | length 1061.1
  Top Layer w8: U9.23@347.76,368.39 347.76,420.1 424.86,497.2 831.8,497.2 v2(845,484) ; v2(1009,497) 1100,497 1173.6,570.6 1173.6,602.94 1194.88,624.22 U8.31@1242.75,624.22
  Bottom Layer w8: v2(845,484) 858,497 v2(1009,497)
DC_FB: C23.1 R23.1 R31.2 U9.5 | length 1519.9
  Top Layer w8: v2(1744,356) R23.1@1744,431.5
  Top Layer w15: v2(626.2,732.46) 629.25,729.41 U9.5@629.25,667.61
  Bottom Layer w8: v2(626.2,732.46) 626.2,644.2 622,640 637.62,624.38 C23.1@669,624.38 670,625.38 R31.2@721,625.38 820.38,625.38 873,678 987.96,678 1284.56,381.4 1718.6,381.4 v2(1744,356)
DIR: C36.1 J2.1 R43.2 U9.15 | length 396.1
  Top Layer w8: J2.1@73,794 75.38,791.62 R43.2@160,791.62 323,791.62 C36.1@373.62,741 373.62,667.88 U9.15@373.35,667.61
DVDD: C13.1 U8.33 | length 94.6
  Top Layer w8: U8.33@1281.75,623.85 U8.33@1282.12,624.22
  Top Layer w10: C13.1@1265.5,537 1282.12,553.62 U8.33@1282.12,624.22
EN_GATE: J5.7 U8.30 U9.3 | length 1684.3
  Top Layer w8: U9.3@680.43,667.61 680.43,616.57 688.48,608.52 848.52,608.52 857,617 v2(860,617) ; v2(985,521) 1097.34,521 1157.8,581.46 1157.8,609.49 1198.12,649.81 U8.30@1217.16,649.81
  Bottom Layer w8: v2(860,617) 860,586 925,521 v2(985,521) 988.8,521 989,521.2 989.4,520.8 1033.44,520.8 1253.04,301.2 1590.8,301.2 1625,267 1625,114 J5.7@1670,69
FAULT: R36.2 R40.1 U8.25 U9.2 | length 2108.9
  Top Layer w8: U9.2@706.02,667.61 706.02,632.3 714,624.32 819.32,624.32 898.38,703.38 R36.2@922,703.38 949.55,675.83 1002.83,675.83 1015.4,688.4 1102.46,688.4 1151,736.94 v2(1151,738) 1161.24,748.24 U8.25@1217.16,748.24 ; v2(2054,56) R40.1@2164.5,56
  Top Layer w10: R40.1@2164.5,56 R40.1@2172.5,64
  Bottom Layer w8: v2(1151,738) 1151,604.34 1310.34,445 1833.68,445 2054,224.68 v2(2054,56)
GH_A: R5.2 R7.2 U8.6 | length 1013.5
  Top Layer w10: U8.6@1445.5,748.24 1640.24,748.24 1794,902 v2(1794,972) 1936.8,972 2033.45,1068.65 R7.2@2033.45,1112.72 ; v2(1730,970) 1730.45,970.45 R5.2@1730.45,1112.72
  Bottom Layer w10: v2(1730,970) 1792,970 v2(1794,972)
GH_B: R1.2 R3.2 U8.15 | length 648.8
  Top Layer w10: R1.2@1125.45,1112.72 1125.45,1072.55 1155.92,1042.08 1266.26,1042.08 1330,978.34 v2(1330,951) 1330,899 1329.9,898.89 1339.29,889.5 1339.29,889.26 1341.17,887.37 U8.15@1341.17,852.57 ; v2(1428,1026) R3.2@1428,1113.2
  Bottom Layer w10: v2(1330,951) 1403.07,951 1428,975.93 v2@1428,1015
GH_C: R9.2 R11.2 U8.16 | length 1112.1
  Top Layer w10: R9.2@520,1113.2 519.68,1112.88 519.68,999.32 546.8,972.2 805.52,972.2 822,988.68 ; R11.2@822.07,1093.2 822.07,988.75 822,988.68 ; U8.16@1321.49,852.57 1321.49,882.13 1214.94,988.68 822,988.68
GL_A: R6.2 R8.2 U8.8 | length 906
  Top Layer w10: U8.8@1445.5,787.61 1623.61,787.61 1668.45,832.45 v2@1668.45,1006 ; v2@1667,1006 v2(1668,1007) ; v2@1668.45,1007 R6.2@1668.45,1112.72 ; v2@1864,1005.27 v2@1865.73,1007 ; v2(1864,1007) v2@1865.73,1007 ; R8.2@1971.45,1112.72 1971.45,1054.45 1924,1007 v2@1865.73,1007
  Bottom Layer w10: v2(1668,1007) v2(1864,1007)
GL_B: R2.2 R4.2 U8.13 | length 684
  Top Layer w10: R2.2@1063.45,1112.72 1063.45,1080.82 1120,1024.28 1252.6,1024.28 1294.9,981.98 v2(1294.9,978.37) ; v2(1366,1026) R4.2@1366,1113.2 ; U8.13@1380.54,852.57 1380.54,940.54 1393,953 v2(1393,976)
  Bottom Layer w10: v2(1294.9,978.37) 1390.63,978.37 v2(1393,976) 1393,999 v2(1366,1026)
GL_C: R10.2 R12.2 U8.18 | length 1175.6
  Top Layer w10: R10.2@458,1113.2 457.68,1112.88 457.68,1014.32 520.2,951.8 776.2,951.8 v2(781,947) 837.68,947 846,938.68 1214.59,938.68 1282.12,871.15 U8.18@1282.12,852.57 ; R12.2@760.39,1112.72 760.39,1054.61 780,1035 v2(780,997)
  Bottom Layer w10: v2(780,997) 781,996 v2(781,947)
GND: C1.2 C2.2 C4.2 C5.2 C6.2 C7.2 C8.2 C9.2 C10.1 C13.2 C14.2 C15.2 C16.2 C17.2 C23.2 C24.2 C26.2 C27.2 C28.2 C29.2 C30.2 C31.2 C32.2 C33.2 C34.2 C35.2 C36.2 C37.2 C38.2 C39.2 C40.2 C41.2 C43.2 C44.2 C45.2 C46.2 C47.2 C48.2 D1.1 D4.1 J1.3 J2.2 J3.4 J4.2 pad.1@106.83,2233.05 R13.2 R15.2 R18.2 R20.1 R21.1 R22.1 R31.1 R46.1 S1.1 U5.7 U5.9 U8.32 U8.40 U8.41@1331.33,738.4 U9.4 U9.22 U9.30 U10.2 | length 3239.3
  Top Layer w8: C13.2@1202.5,537 1205.5,540 1262.43,596.93 U8.32@1262.43,624.22 1262.43,669.5 v1(1304.36,711.43) U8.41@1331.33,738.4 v1(1358.3,711.43) 1419.91,649.81 U8.40@1419.91,624.22
  Top Layer w10: C35.2@957.62,1084.82 984.82,1084.82 1002,1102 1002,1165.28 996.28,1171 U10.2@970.29,1171
  Top Layer w12: 526.89,206.89 U9.30@526.89,368.39 ; C7.2@1877.36,564.15 C8.2@1926.36,564.15 1940.78,549.73 U5.7@1989.23,549.73 2031.55,549.73 U5.9@2044.35,562.53
  Top Layer w15: J2.2@73,694 137,630 C40.2@157.38,630 C39.2@157.38,530 ; C38.2@171.14,368.21 171.14,330.86 v2(184,318) ; C28.2@266.32,202.14 321.82,202.14 v2(322.32,202.63) 322,202.95 322,368.23 U9.22@322.17,368.39 ; v2(286,741) C36.2@326.38,741 ; v2(431,781) 466.62,781 C44.2@467,780.62 ; C45.2@523,781.62 523,819 v2(523,817) ; C43.2@590,782.24 C43.2@593.24,779 ; C43.2@593.24,789 v2(653.56,789) ; U9.4@654.84,667.61 654.84,716.19 C30.2@686.65,748 ; C37.2@700,239.38 728,211.38 v2(728,195) ; C34.2@802,290.38 C34.2@801.62,290 802.24,289.38 R46.1@802.24,236 v2(842,236) ; v2(848,95) S1.1@940.95,95 ; v2(957.62,1016.38) C35.2@957.62,1084.82 ; C24.2@1050.57,728 v2(1009,728) ; v2@1111,318 v2(1110,317) C46.2@1246.03,317 ; C47.2@1293.28,384.81 1293.28,428.12 1297.97,432.81 1297.97,452.97 v2(1317,472) ; v2(1009,728) 1008,728 1009,729 v2(1009,728)
  Top Layer w20: v2(686,789) 686,748.65 C30.2@686.65,748 ; v2(1204,592) 1204,547.5 1201,544.5 1205.5,540 C13.2@1205.5,537 ; v2(2310.74,87.26) D4.1@2310.74,142.78
  GND w15: 957,872 957.62,872.62 v2(957.62,1016.38)
  Bottom Layer w10: R18.2@2072,1095.62 2053.8,1113.82 2053.8,1248.8 2068,1263 2134,1263 2135,1264 2164,1264
  Bottom Layer w15: C27.2@266.32,193.63 275.32,202.63 v2(322.32,202.63) ; C33.2@523,781.62 523,819 v2(523,817) ; C31.2@671,743 686,758 v2(686,789) ; C31.2@671.93,742.07 669,739.15 C23.2@669,671.62 670,672.62 R31.1@721,672.62
  Bottom Layer w20: v2(423,191) 560.61,191 C29.2@561.32,190.29
  other v1: 2044.35,525.13 2021.71,562.53 2066.98,562.53 2044.35,599.93 1304.36,666.55 1358.3,666.55 1259.48,711.43 1403.18,711.43 1259.48,765.36 1304.36,765.36 1358.3,765.36 1403.18,765.36 1304.36,810.25 1358.3,810.25 2211,1205 2271,1205 2331,1205 2391,1205 2451,1205 2511,1205 2211,1265 2271,1265 2331,1265 2391,1265 2451,1265 2511,1265 2211,1325 2271,1325 2331,1325 2391,1325 2451,1325 2511,1325 2211,1385 2271,1385 2331,1385 2391,1385 2451,1385 2511,1385 2211,1445 2271,1445 2331,1445 2391,1445 2451,1445 2511,1445 2211,1505 2271,1505 2331,1505 2391,1505 2451,1505 2511,1505 2211,1565 2271,1565 2331,1565 2391,1565 2451,1565 2511,1565 2211,1625 2271,1625 2211,1685 2271,1685 2211,1745 2271,1745 2211,1805 2271,1805 2361,1835 2421,1835 2481,1835 2211,1865 2271,1865 2301,1895 2361,1895 2421,1895 2481,1895 2181,1955 2241,1955 2301,1955 2361,1955 2421,1955 2481,1955 2121,2015 2181,2015 2241,2015 2301,2015 2361,2015 2421,2015 2481,2015 2061,2075 2121,2075 2181,2075 2241,2075 2301,2075 2361,2075 2421,2075 2481,2075 2061,2135 2121,2135 2181,2135 2241,2135 2301,2135 2361,2135 2421,2135 2481,2135 2061,2195 2121,2195 2181,2195 2241,2195 2301,2195 2361,2195 2421,2195 2481,2195 2061,2255 2121,2255 2181,2255 2241,2255 2301,2255 2361,2255 2421,2255 2481,2255 2061,2315 2121,2315 2181,2315 2241,2315 2301,2315 2361,2315 2421,2315 2481,2315
  other v2: 1198,142 1238,142 950,150 990,150 1454,486 1514,486 1574,486 1634,486 1694,486 374,531 326,592 1767.95,603.69 1768,651 207,683 1727,708 241,758 385,837 425,837 2179,1001 2216,1001 2253,1001 2179,1038 2216,1038 2253,1038 2179,1075 2216,1075 2253,1075
HA: C40.1 R25.1 R52.1 U9.19 | length 967.8
  Top Layer w8: C40.1@204.62,630 222.62,612 v2(247,612) 270.98,635.98 U9.19@270.98,667.61
  Bottom Layer w8: R52.1@212,630 R52.1@204.62,630 222.62,612 v2(247,612) 363.2,495.8 799.2,495.8 838.2,456.8 941.75,456.8 R25.1@967.34,431.21
HB: C39.1 R28.1 R51.1 U9.18 | length 1077.5
  Top Layer w8: C39.1@204.62,530 v2(251,530) 296.57,575.57 U9.18@296.57,667.61
  Bottom Layer w8: v2(251,530) 251,526.38 R51.1@204.62,480 792.65,480 885.65,387 948,387 959.79,375.21 R28.1@966.62,375.21
HC: C38.1 R30.1 R50.1 U9.20 | length 1027.9
  Top Layer w8: v2(216,325) 218.38,327.38 C38.1@218.38,366.38 ; C38.1@218.38,368.21 C38.1@218.38,366.38 ; U9.20@270.98,368.39 268.97,366.38 C38.1@218.38,366.38
  Bottom Layer w8: R50.1@204.62,380 204.62,336.38 v2(216,325) 355.2,464.2 786.11,464.2 926.51,323.8 960.03,323.8 R30.1@967.62,316.21
IA_IDC: C43.1 J5.12 R55.2 U9.6 U9.7 | length 1910.8
  Top Layer w8: U9.7@578.07,667.61 U9.6@603.66,667.61 603.66,698.34 603.93,698.61 603.93,721.07 594,731 594,733 566.39,760.61 566.39,802.88 576.51,813 866.1,813 885.1,794 982,794 v2(1009,767) 1013,771 1043.13,771 R55.2@1049.94,777.81
  Bottom Layer w8: v2(1009,767) 1040.5,735.5 1040.5,647.81 1291.11,397.2 1747.8,397.2 1871,274 1871,170 J5.12@1870,169
IB: C45.1 J5.13 R54.2 U9.9 | length 2202.5
  Top Layer w8: U9.9@526.89,667.61 523,671.5 C45.1@523,734.38 549.39,760.77 549.39,808.39 550.59,808.39 550.59,809.42 569.96,828.8 872.64,828.8 882.44,819 v2(910,819) 912,821 1043.13,821 R54.2@1049.94,827.81
  Bottom Layer w8: v2(910,819) 1004.87,819 1056.3,767.57 1056.3,654.35 1297.65,413 1788,413 1925.72,275.28 1925.72,113.28 J5.13@1970,69
IC: C44.1 J5.14 R53.2 U9.10 | length 2171.9
  Top Layer w8: U9.10@501.3,667.61 501.3,698.34 469.64,730 467,730 C44.1@467,733.38 490.8,757.18 490.8,820.46 514.94,844.6 965.6,844.6 v2(998,877) 998.81,877.81 R53.2@1049.94,877.81
  Bottom Layer w8: v2(998,877) 1073,802 1073,660 1303.8,429.2 1815.8,429.2 1970,275 J5.14@1970,169
INH_A: J5.4 U8.34 U9.16 | length 1812.1
  Top Layer w8: U9.16@347.76,667.61 347.76,636.87 455.63,529 928,529 985,472 v2(988,472) 1254,472 1258,476 1261,473 1302.8,514.8 1302.8,623.22 U8.34@1301.8,624.22
  Bottom Layer w8: v2(988,472) 1054,472 1275.55,250.45 1423.55,250.45 1470,204 J5.4@1470,169
INH_B: J5.2 R29.1 U9.24 | length 1246.5
  Top Layer w8: U9.24@373.35,368.39 373.35,423.35 431.4,481.4 779.6,481.4 898,363 v2(922,363) 922,366 924.16,368.16 R29.1@959.57,368.16
  Bottom Layer w8: v2(922,363) 938.2,346.8 1122.2,346.8 1300,169 J5.2@1370,169
INH_C: J5.6 U8.38 U9.32 | length 1588.2
  Top Layer w8: U9.32@578.07,368.39 578.07,417.07 610.8,449.8 732.54,449.8 905.34,277 v2(1322,277) 1325,274 1380.54,329.54 U8.38@1380.54,624.22
  Bottom Layer w8: v2(1322,277) 1326.8,281.8 1519.2,281.8 1570,231 J5.6@1570,169
INL_A: J5.3 R27.1 U9.17 | length 1573.6
  Top Layer w8: U9.17@322.17,667.61 322.17,636.87 446.04,513 883,513 963.79,432.21 963.79,431.21 R27.1@967.34,431.21 947.13,411 v2(914,411) ; R27.1@964.77,433.77 R27.1@966,435
  Bottom Layer w8: v2(914,411) 914,408 918.8,403.2 1045.14,403.2 1045.64,403.7 1046.14,403.2 1092.8,403.2 1261.35,234.65 1387.35,234.65 1420,202 1420,119 J5.3@1470,69
INL_B: J5.1 R32.1 U9.25 | length 1323.2
  Top Layer w8: U9.25@398.94,368.39 398.94,422.94 441.6,465.6 750.4,465.6 v2(866,350) 899.79,316.21 R32.1@967.62,316.21
  Bottom Layer w8: v2(866,350) 872,350 936.5,285.5 1128.5,285.5 1345,69 J5.1@1370,69
INL_C: J5.5 U8.39 U9.37 | length 1467.1
  Top Layer w8: U9.37@706.02,368.39 706.02,412.02 714,420 740,420 906.8,253.2 1352,253.2 1400.23,301.43 ; U8.39@1400.23,624.22 1400.23,301.43 ; v2(1467,254) 1447.65,254 1400.23,301.43
  Bottom Layer w8: v2(1467,254) 1521,200 1521,118 J5.5@1570,69
LED: R41.1 U9.33 | length 1780.6
  Top Layer w8: U9.33@603.66,368.39 603.66,324.34 639.04,288.96 639.04,181.04 v2(630,172) ; v2(809,204) 810.8,202.2 1246.8,202.2 1328,121 2032,121 2103,192 R41.1@2103,194.5
  Bottom Layer w8: v2(630,172) 646,156 761,156 v2(809,204)
MU: U1.3 U1.4 U1.5 U1.6 U1.7 U1.8 U1.9 U1.10 U1.11 U2.3 U2.4 U2.5 U2.6 U2.7 U2.8 U2.9 U2.10 U2.11
MV: U3.3 U3.4 U3.5 U3.6 U3.7 U3.8 U3.9 U3.10 U3.11 U4.3 U4.4 U4.5 U4.6 U4.7 U4.8 U4.9 U4.10 U4.11
MW: U6.3 U6.4 U6.5 U6.6 U6.7 U6.8 U6.9 U6.10 U6.11 U7.3 U7.4 U7.5 U7.6 U7.7 U7.8 U7.9 U7.10 U7.11
NetC3_1: C3.1 L1.1 U5.8 | length 162.3
  Top Layer w12: 1908,520 1912.14,524.14 U5.8@1989.23,524.14
  Bottom Layer w12: v2(1942,480) 1943.45,478.55 C3.1@2020.72,478.55
NetC3_2: C3.2 U5.1 | length 143.5
  Top Layer w12: U5.1@2099.46,524.14 2114.76,524.14 v2(2146,492.9)
  Bottom Layer w12: C3.2@2067.97,478.55 2131.65,478.55 v2(2146,492.9)
NetC7_1: C7.1 R19.1 | length 53.9
  Top Layer w12: C7.1@1877.36,611.4 1877.36,663.4 R19.1@1878.74,664.77
NetC8_1: C8.1 R19.2 U5.6 | length 131.3
  Top Layer w12: R19.2@1925.99,664.77 1926.36,664.4 C8.1@1926.36,611.4 1926.6,611.4 1962.68,575.32 U5.6@1989.23,575.32
NetC11_2: C11.2 U8.3 | length 93.4
  Top Layer w10: U8.3@1445.5,689.18 1474.32,689.18 C11.2@1520,643.5
NetC12_1: C12.1 U8.1 | length 120.4
  Top Layer w8: C12.1@1442.5,557 1468.2,582.7 1468.2,640.04 1458.43,649.81 U8.1@1445.5,649.81
NetC12_2: C12.2 U8.2 | length 147.3
  Top Layer w10: U8.2@1445.5,669.5 1462.5,669.5 1485,647 1485,581 1505.5,560.5 C12.2@1505.5,557
NetC24_1: C24.1 R56.2 U8.24 | length 271.9
  Top Layer w8: R56.2@972,703.38 972.82,704.2 1074.01,704.2 C24.1@1097.81,728 1101.69,728 1141.61,767.92 U8.24@1217.16,767.92
NetC26_1: C26.1 U9.29 | length 124.4
  Top Layer w15: C26.1@470,257 501.3,288.3 U9.29@501.3,368.39
NetC27_1: C27.1 C28.1 C29.1 C30.1 C31.1 C32.1 R37.2 U9.1 U9.21 U9.31 | length 539.9
  Top Layer w15: v2(202,255) 256.19,255 C28.1@266.32,265.13 ; C28.1@266,281.5 296.57,312.07 U9.21@296.57,368.39 ; U9.31@552.48,368.39 552.48,270.62 C32.1@561.32,261.78 v2(608,261.78) ; U9.1@731.61,667.61 731.61,729.97 C30.1@749.65,748
  Bottom Layer w15: v2(202,255) 220.63,273.63 C27.1@266.32,273.63 C27.1@269.67,270.29 ; C29.1@561.32,270.29 569.82,261.78 v2(608,261.78)
  other v2: 762,787 797,787
NetC46_1: C46.1 R30.2 R32.2 U8.37 | length 682.8
  Top Layer w8: R32.2@1014.86,316.21 1021.65,323 v2(1059,323) 1078,342 1268.27,342 C46.1@1293.27,317 1295.34,317 1360.86,382.51 U8.37@1360.86,624.22
  Bottom Layer w8: R30.2@1014.86,316.21 1021.65,323 v2(1059,323)
NetC47_1: C47.1 R28.2 R29.2 U8.36 | length 645.3
  Top Layer w8: R29.2@1013.86,375.21 v2@1058.21,375.21 ; v2(1058,371) 1058,375 v2@1058.21,375.21 ; U8.36@1341.17,624.22 1341.17,609.25 1341.25,609.18 1341.25,385.25 1314,358 1272.84,358 C47.1@1246.03,384.81 1067.81,384.81 v2@1058.21,375.21
  Bottom Layer w8: R28.2@1013.86,375.21 1057.79,375.21 1058,375 v2(1058,371)
NetC48_1: C48.1 R25.2 R27.2 U8.35 | length 502.3
  Top Layer w8: R27.2@1014.58,431.21 1018.79,427 v2(1056,427) 1240.22,427 C48.1@1246.03,432.81 1246.03,434.69 1321.49,510.14 U8.35@1321.49,624.22
  Bottom Layer w8: R25.2@1014.58,431.21 1019.79,426 1020.79,427 v2(1056,427)
NetD2_1: D2.1 R40.2 | length 79.5
  Top Layer w8: R40.2@2235.5,64 2235.5,140 D2.1@2238,142.5
NetD3_1: D3.1 R41.2 | length 71.1
  Top Layer w8: R41.2@2113,141.5 D3.1@2170,141.5
  Top Layer w10: R41.2@2103,131.5 R41.2@2113,141.5
NetD4_2: D4.2 R38.1 | length 62.4
  Top Layer w15: R38.1@2305.5,266 2310.74,260.75 D4.2@2310.74,205.77
NetJ1_2: J1.2 R45.2 | length 81.3
  Top Layer w8: J1.2@1148,69 1148,149.38 R45.2@1148.62,150
NetR1_1: R1.1 U3.1 | length 502.7
  Top Layer w8: U3.1@1076.73,1600.89 1076.73,1616.94 1082.3,1622.52 1106.3,1622.52 1118.86,1609.96 1118.86,1596.07
  Top Layer w10: 1118.86,1596.07 1118.86,1182.31 R1.1@1125.45,1175.72
NetR2_1: R2.1 U3.22 | length 245.6
  Top Layer w10: R2.1@1063.45,1175.72 1076.73,1188.99 U3.22@1076.73,1415.85
NetR3_1: R3.1 U4.1 | length 502.7
  Top Layer w8: U4.1@1379.28,1601.37 1379.28,1617.43 1384.85,1623 1408.85,1623 1421.41,1610.44 1421.41,1596.56
  Top Layer w10: 1421.41,1596.56 1421.41,1182.79 R3.1@1428,1176.2
NetR4_1: R4.1 U4.22 | length 245.6
  Top Layer w10: R4.1@1366,1176.2 1379.28,1189.47 U4.22@1379.28,1416.33
NetR5_1: R5.1 U1.1 | length 502.7
  Top Layer w8: U1.1@1681.73,1600.89 1681.73,1616.94 1687.3,1622.52 1711.3,1622.52 1723.86,1609.96 1723.86,1596.07
  Top Layer w10: 1723.86,1596.07 1723.86,1182.31 R5.1@1730.45,1175.72
NetR6_1: R6.1 U1.22 | length 245.6
  Top Layer w10: R6.1@1668.45,1175.72 1681.73,1188.99 U1.22@1681.73,1415.85
NetR7_1: R7.1 U2.1 | length 495.6
  Top Layer w8: U2.1@1984.73,1600.89 1984.73,1616.94 1990.3,1622.52 2018.14,1622.52 2026.86,1613.8 2026.86,1596.07
  Top Layer w10: R7.1@2026.86,1182.31 2026.86,1596.07
NetR8_1: R8.1 U2.22 | length 245.6
  Top Layer w10: R8.1@1971.45,1175.72 1984.73,1188.99 U2.22@1984.73,1415.85
NetR9_1: R9.1 U6.1 | length 502.7
  Top Layer w8: U6.1@471.28,1601.37 471.28,1617.43 476.85,1623 500.85,1623 513.41,1610.44 513.41,1596.56
  Top Layer w10: 513.41,1596.56 513.41,1182.79 R9.1@520,1176.2
NetR10_1: R10.1 U6.22 | length 245.6
  Top Layer w10: R10.1@458,1176.2 471.28,1189.47 U6.22@471.28,1416.33
NetR11_1: R11.1 U7.1 | length 502.7
  Top Layer w8: U7.1@773.67,1600.89 773.67,1616.94 779.24,1622.52 803.24,1622.52 815.8,1609.96 815.8,1596.07
  Top Layer w10: 815.8,1596.07 815.8,1182.31 R11.1@822.39,1175.72
NetR12_1: R12.1 U7.22 | length 245.6
  Top Layer w10: R12.1@760.39,1175.72 773.67,1188.99 U7.22@773.67,1415.85
NetR14_1: R14.1 R20.2 U5.5 | length 184.6
  Top Layer w12: R14.1@1925.62,725.31 R20.2@1983.38,725.31 1989.23,719.46 U5.5@1989.23,600.91
NetR16_1: R16.1 R21.2 U5.3 | length 130.8
  Top Layer w12: U5.3@2099.46,575.32 2121.01,575.32 2136.83,591.15 R16.1@2161,591.15
  Top Layer w20: R16.1@2161,591.15 R21.2@2161,653.91
NetR22_2: R22.2 U5.4 | length 69.3
  Top Layer w12: U5.4@2099.46,600.91 2099.46,662.95 R22.2@2104.62,668.11
NetR24_2: R24.2 U8.20 | length 618.8
  Top Layer w10: v2(717,927) 721.8,922.2 832.8,922.2 840,915 1204.27,915 1242.75,876.52 U8.20@1242.75,852.57
  Bottom Layer w10: R24.2@676,944.38 693.38,927 v2(717,927)
NetR26_2: R26.2 U8.11 | length 118.4
  Top Layer w10: U8.11@1419.91,852.57 v2(1420,925) v2(1420,925)
  Bottom Layer w10: R26.2@1378.62,914 1409,914 v2(1420,925)
NetR34_1: R34.1 U8.27 | length 145.4
  Top Layer w8: R34.1@1098.62,644 1123.34,644 1188.21,708.87 U8.27@1217.16,708.87
NetR35_1: R35.1 U8.28 | length 157.5
  Top Layer w8: R35.1@1098.62,595 1192.81,689.18 U8.28@1217.16,689.18
NetR42_2: R42.2 U10.3 | length 760.5
  Top Layer w8: U10.3@980.29,1196.73 1002.09,1196.73 1019.2,1179.62 1019.2,1024.49 v2(1011.09,1016.38)
  Bottom Layer w8: R42.2@582,782.24 640.66,840.9 872.9,840.9 1011.09,979.09 v2(1011.09,1016.38)
NetR53_1: R53.1 U8.21 | length 141
  Top Layer w8: R53.1@1097.18,877.81 1148.01,826.98 U8.21@1217.16,826.98
NetR54_1: R54.1 U8.22 | length 128.5
  Top Layer w8: R54.1@1097.18,827.81 1117.7,807.29 U8.22@1217.16,807.29
NetR55_1: R55.1 U8.23 | length 124
  Top Layer w8: R55.1@1097.18,777.81 1129.16,777.81 1138.95,787.61 U8.23@1217.16,787.61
